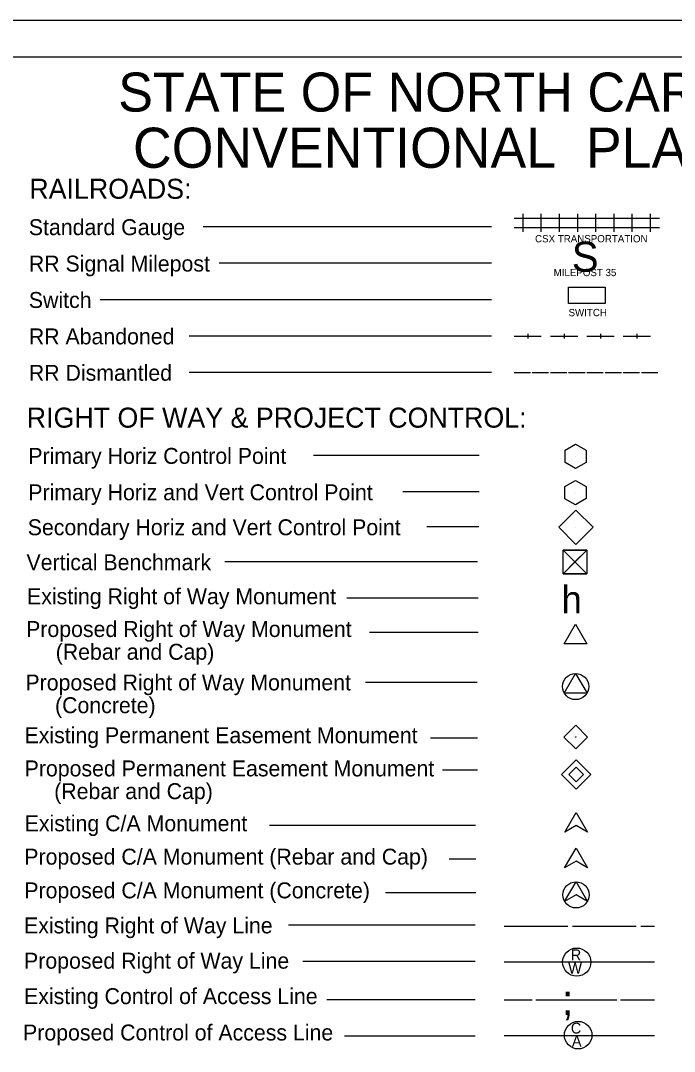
# Model space of a CAD drawing. Extents: x 2058169 to 2059852, y 675171 to 676266.
# Drawn here: x 2058730 to 2059089, y 675700 to 676266 of the extents above; entities that cross this region are included whole.
import ezdxf

# ---------------------------------------------------------------- set-up
doc = ezdxf.new("R2010")
doc.units = 0
for name, color, linetype in [('Old_Level_42', 7, 'Continuous'), ('Prop ROW Permanent Easement CELL', 7, 'Continuous'), ('Sheet Block Title CELL', 7, 'Continuous'), ('Sheet Clip Boundary CELL', 7, 'Continuous'), ('Sheet Sticker Exception Certification CELL', 7, 'Continuous'), ('Sheet Symbology CELL', 7, 'Continuous')]:
    doc.layers.add(name, color=color, linetype=linetype)

msp = doc.modelspace()

# ---------------------------------------------------------------- linework, layer by layer
at = {"layer": 'Old_Level_42'}
for p, q in [((2059034.71, 676026.77), (2059034.71, 676026.77)), ((2059034.7, 676006.81), (2059034.7, 676006.81)), ((2059034.84, 675987.73), (2059034.84, 675987.73)), ((2059034.34, 675968.73), (2059034.34, 675968.73)), ((2059034.8, 675872.51), (2059034.8, 675872.51))]:
    msp.add_line(p, q, dxfattribs=at)
for points in [[(2059034.71, 676020.12), (2059028.92, 676023.41), (2059028.92, 676030.07), (2059034.71, 676033.43), (2059040.51, 676030.14), (2059040.51, 676023.41), (2059034.71, 676020.12)], [(2059040.81, 675975.21), (2059027.84, 675962.24), (2059034.33, 675968.72), (2059040.81, 675962.24), (2059027.84, 675975.21)], [(2059034.33, 675968.72), (2059040.81, 675975.21), (2059027.84, 675975.21), (2059034.33, 675968.72)], [(2059034.33, 675968.72), (2059027.84, 675962.24), (2059040.81, 675962.24), (2059034.33, 675968.72)]]:
    msp.add_lwpolyline(points, dxfattribs=at)
for points in [[(2059028.87, 676010.18), (2059034.74, 676013.45), (2059040.6, 676010.23), (2059040.51, 676003.51), (2059034.65, 676000.1), (2059028.87, 676003.37)], [(2059025.43, 675987.76), (2059034.89, 675997.22), (2059044.36, 675987.75), (2059034.91, 675978.29)], [(2059027.84, 675975.21), (2059040.81, 675975.21), (2059040.81, 675962.24), (2059027.84, 675962.24)], [(2059028.31, 675872.51), (2059034.8, 675879.01), (2059041.3, 675872.51), (2059034.8, 675866.02)]]:
    msp.add_lwpolyline(points, close=True, dxfattribs=at)
msp.add_circle((2059034.8, 675872.51), 0.126, dxfattribs=at)
at = {"layer": 'Prop ROW Permanent Easement CELL'}
msp.add_line((2059034.98, 675851.91), (2059034.98, 675851.91), dxfattribs=at)
for points in [[(2059034.98, 675859.96), (2059043.03, 675851.9), (2059034.98, 675843.85), (2059026.93, 675851.9)], [(2059034.98, 675855.93), (2059039.01, 675851.9), (2059034.98, 675847.88), (2059030.96, 675851.9)]]:
    msp.add_lwpolyline(points, close=True, dxfattribs=at)
at = {"layer": 'Sheet Block Title CELL'}
msp.add_lwpolyline([(2058181.54, 675191.1), (2059847.52, 675191.11), (2059847.54, 676246.1), (2058181.54, 676246.1)], close=True, dxfattribs=at)
at = {"layer": 'Sheet Clip Boundary CELL'}
msp.add_line((2059852.04, 676266.1), (2058168.54, 676266.1), dxfattribs=at)
at = {"layer": 'Sheet Sticker Exception Certification CELL'}
msp.add_lwpolyline([(2058168.54, 675171.1), (2059852.04, 675171.1), (2059852.04, 676266.1), (2058168.54, 676266.1)], close=True, dxfattribs=at)
at = {"layer": 'Sheet Symbology CELL'}
for p, q in [((2059000.87, 676157.53), (2059010.87, 676157.53)), ((2059005.87, 676150.03), (2059005.87, 676160.03)), ((2059010.87, 676157.53), (2059020.87, 676157.53)), ((2059015.87, 676150.03), (2059015.87, 676160.03)), ((2059020.87, 676157.53), (2059030.87, 676157.53)), ((2059025.87, 676150.03), (2059025.87, 676160.03)), ((2059030.87, 676157.53), (2059040.87, 676157.53)), ((2059035.87, 676150.03), (2059035.87, 676160.03)), ((2059040.87, 676157.53), (2059050.87, 676157.53)), ((2059045.87, 676150.03), (2059045.87, 676160.03)), ((2059050.87, 676157.53), (2059060.87, 676157.53)), ((2059055.87, 676150.03), (2059055.87, 676160.03)), ((2059060.87, 676157.53), (2059070.87, 676157.53)), ((2059065.87, 676150.03), (2059065.87, 676160.03)), ((2059070.87, 676157.53), (2059080.87, 676157.53)), ((2059075.87, 676150.03), (2059075.87, 676160.03)), ((2058988.47, 676152.77), (2058830.06, 676152.77)), ((2059000.87, 676152.53), (2059010.87, 676152.53)), ((2059010.87, 676152.53), (2059020.87, 676152.53)), ((2059020.87, 676152.53), (2059030.87, 676152.53)), ((2059030.87, 676152.53), (2059040.87, 676152.53)), ((2059040.87, 676152.53), (2059050.87, 676152.53)), ((2059050.87, 676152.53), (2059060.87, 676152.53)), ((2059060.87, 676152.53), (2059070.87, 676152.53)), ((2059070.87, 676152.53), (2059080.87, 676152.53)), ((2058988.47, 676132.77), (2058838.92, 676132.77)), ((2058988.47, 676112.77), (2058773.56, 676112.77)), ((2059008.37, 676094.02), (2059008.37, 676091.52)), ((2059028.37, 676094.02), (2059028.37, 676091.52)), ((2059048.37, 676094.02), (2059048.37, 676091.52)), ((2059068.37, 676094.02), (2059068.37, 676091.52)), ((2058988.47, 676092.77), (2058822.31, 676092.77)), ((2059000.87, 676092.77), (2059015.87, 676092.77)), ((2059020.87, 676092.77), (2059035.87, 676092.77)), ((2059040.87, 676092.77), (2059055.87, 676092.77)), ((2059060.87, 676092.77), (2059075.87, 676092.77)), ((2058988.47, 676072.77), (2058822.31, 676072.77)), ((2058988.47, 676072.77), (2058822.31, 676072.77)), ((2059000.87, 676072.77), (2059009.87, 676072.77)), ((2059010.87, 676072.77), (2059019.87, 676072.77)), ((2059020.87, 676072.77), (2059029.87, 676072.77)), ((2059030.87, 676072.77), (2059039.87, 676072.77)), ((2059040.87, 676072.77), (2059049.87, 676072.77)), ((2059050.87, 676072.77), (2059059.87, 676072.77)), ((2059060.87, 676072.77), (2059069.87, 676072.77)), ((2059070.87, 676072.77), (2059079.87, 676072.77)), ((2058981.78, 676027.15), (2058890.75, 676027.15)), ((2058981.78, 676007.15), (2058939.86, 676007.15)), ((2058981.47, 675987.94), (2058952.92, 675987.94)), ((2058980.78, 675968.72), (2058841.94, 675968.72)), ((2058981.09, 675948.74), (2058909.04, 675948.74)), ((2058981.19, 675929.95), (2058921.46, 675929.95)), ((2059034.71, 675927.34), (2059034.71, 675927.34)), ((2058980.69, 675902.55), (2058919.2, 675902.55)), ((2059034.73, 675900.28), (2059034.73, 675900.28)), ((2058980.77, 675871.86), (2058954.98, 675871.86)), ((2058980.77, 675854.24), (2058961.49, 675854.24)), ((2059028.71, 675820.33), (2059034.96, 675831.13)), ((2059034.96, 675831.13), (2059041.21, 675820.33)), ((2058979.78, 675824.02), (2058866.54, 675824.02)), ((2059034.96, 675823.93), (2059028.71, 675820.33)), ((2059041.21, 675820.33), (2059034.96, 675823.93)), ((2059028.68, 675800.72), (2059034.93, 675811.52)), ((2059034.93, 675811.52), (2059041.18, 675800.72)), ((2058979.88, 675805.48), (2058965.31, 675805.48)), ((2059034.93, 675804.32), (2059028.68, 675800.72)), ((2059041.18, 675800.72), (2059034.93, 675804.32)), ((2059028.68, 675782.21), (2059034.93, 675793.01)), ((2059034.93, 675793.01), (2059041.18, 675782.21)), ((2058979.88, 675786.98), (2058930.21, 675786.98)), ((2059034.93, 675785.81), (2059028.68, 675782.21)), ((2059041.18, 675782.21), (2059034.93, 675785.81)), ((2058979.44, 675769.2), (2058876.92, 675769.2)), ((2058995.47, 675768.62), (2059030.47, 675768.62)), ((2059032.97, 675768.62), (2059067.97, 675768.62)), ((2059070.47, 675768.62), (2059077.97, 675768.62)), ((2058979.44, 675749.2), (2058884.91, 675749.2)), ((2058995.47, 675749.07), (2059077.97, 675749.07)), ((2058979.44, 675728.07), (2058898.12, 675728.07)), ((2058995.47, 675728.07), (2059010.93, 675728.07)), ((2059012.93, 675728.07), (2059057.34, 675728.07)), ((2059059.34, 675728.07), (2059077.97, 675728.07)), ((2058995.47, 675708.64), (2059077.97, 675708.64)), ((2058979.44, 675708.26), (2058907.79, 675708.26))]:
    msp.add_line(p, q, dxfattribs=at)
for points in [[(2059030.87, 676119.73), (2059050.87, 676119.73), (2059050.87, 676110.63), (2059030.87, 676110.63)], [(2059028.46, 675923.74), (2059034.71, 675934.54), (2059040.96, 675923.74)], [(2059028.48, 675896.68), (2059034.73, 675907.48), (2059040.98, 675896.68)]]:
    msp.add_lwpolyline(points, close=True, dxfattribs=at)
for centre, radius in [((2059034.72, 675900.27), 7.2), ((2059034.93, 675785.81), 7.2), ((2059035.32, 675748.87), 7.75), ((2059036.11, 675708.74), 7.58)]:
    msp.add_circle(centre, radius, dxfattribs=at)

# ---------------------------------------------------------------- texts
for s, height, p in [('STATE OF NORTH CAROLINA, DIVISION OF HIGHWAYS', 21.419, (2058783.41, 676216.12)), ('CONVENTIONAL  PLAN SHEET SYMBOLS', 22.0323, (2058791.54, 676185.24)), ('RAILROADS:', 11, (2058734.59, 676168.22)), ('Standard Gauge', 8.75, (2058734.31, 676148.24)), ('CSX TRANSPORTATION', 4, (2059012.43, 676144.29)), ('S', 16.5, (2059032.63, 676128.14)), ('RR Signal Milepost', 8.75, (2058734.31, 676128.24)), ('MILEPOST 35', 4, (2059022.62, 676125.72)), ('Switch', 8.75, (2058734.31, 676108.24)), ('SWITCH', 4, (2059030.82, 676103.72)), ('RR Abandoned', 8.75, (2058734.31, 676088.24)), ('RR Dismantled', 8.75, (2058734.31, 676068.24)), ('RIGHT OF WAY & PROJECT CONTROL:', 11, (2058733.18, 676042.49)), ('Primary Horiz Control Point', 8.75, (2058734.03, 676022.6)), ('Primary Horiz and Vert Control Point', 8.75, (2058734.03, 676002.6)), ('Secondary Horiz and Vert Control Point', 8.75, (2058733.72, 675983.39)), ('Vertical Benchmark', 8.75, (2058733.03, 675964.17)), ('Existing Right of Way Monument', 8.75, (2058733.34, 675945.46)), ('h', 15, (2059026.94, 675940.56)), ('Proposed Right of Way Monument', 8.75, (2058732.82, 675927.48)), ('     (Rebar and Cap)', 8.75, (2058732.82, 675914.98)), ('Proposed Right of Way Monument', 8.75, (2058732.45, 675898.13)), ('     (Concrete)', 8.75, (2058732.45, 675885.63)), ('Existing Permanent Easement Monument', 8.75, (2058731.96, 675869.14)), ('Proposed Permanent Easement Monument', 8.75, (2058732, 675850.91)), ('     (Rebar and Cap)', 8.75, (2058732, 675838.41)), ('Existing C/A Monument', 8.75, (2058732.03, 675820.74)), ('Proposed C/A Monument (Rebar and Cap)', 8.75, (2058731.82, 675802.43)), ('Proposed C/A Monument (Concrete)', 8.75, (2058731.82, 675783.92)), ('Existing Right of Way Line', 8.75, (2058731.69, 675764.65)), ('Proposed Right of Way Line', 8.75, (2058731.69, 675745.27)), ('R', 6.07, (2059031.98, 675749.78)), ('W', 6.07, (2059030.6, 675742.62)), ('Existing Control of Access Line', 8.75, (2058731.69, 675725.81)), (';', 16.5, (2059027.26, 675719.89)), ('Proposed Control of Access Line', 8.75, (2058731.14, 675705.83)), ('C', 5.94, (2059032.08, 675709.64)), ('A', 5.94, (2059032.68, 675702.5))]:
    msp.add_text(s, height=height, rotation=360, dxfattribs=at).set_placement(p)

doc.saveas('drawing.dxf')
